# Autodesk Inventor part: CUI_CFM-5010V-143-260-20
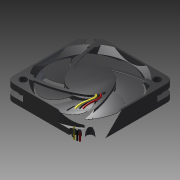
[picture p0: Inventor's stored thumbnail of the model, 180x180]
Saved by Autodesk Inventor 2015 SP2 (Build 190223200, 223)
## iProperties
Created: 2018-02
Part Number: CUI_CFM-5010V-143-260-20
Material: Generic
Document SubType Name: Modeling
Designer: 3dxAdmin
Density: 1 g/cm^3
Appearance: Default
3DX_CUI_Supplier: CUI, Inc
3DX_CUI_Description: 12 V, 58 mA, 50 x 50 x 10 mm, Dc Fan, Tachometer Signal
3DX_CUI_Model Number: CFM-5010V-143-260-20
Author: 3dxAdmin
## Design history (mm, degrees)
feature "Base1"
node "Boss-Extrude9"
